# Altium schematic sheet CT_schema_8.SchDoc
size 277 x 170 mm
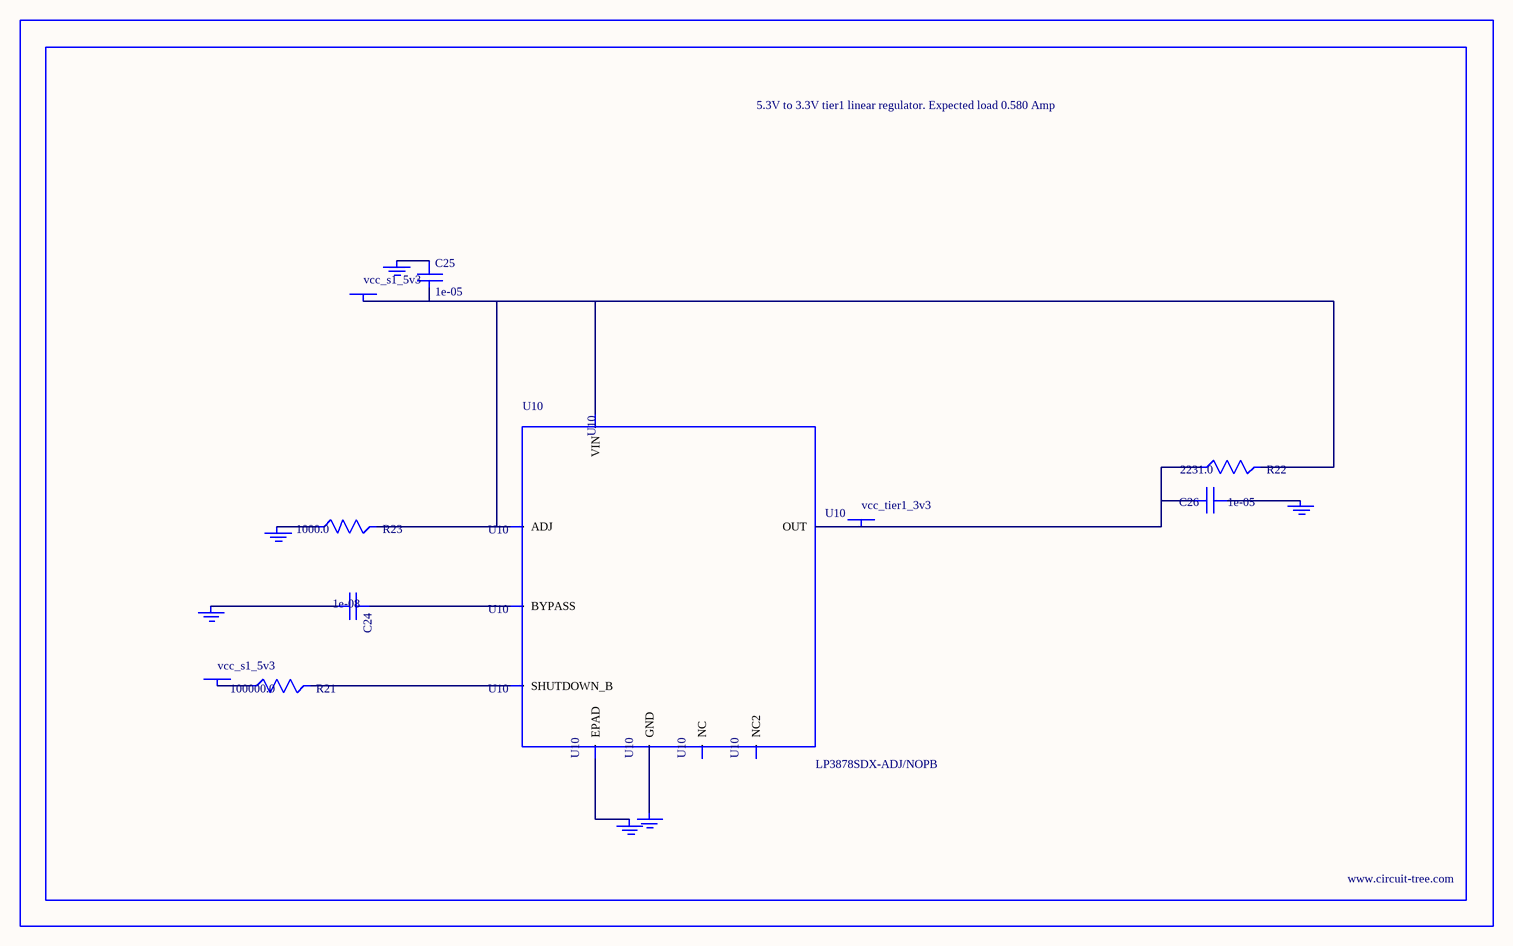
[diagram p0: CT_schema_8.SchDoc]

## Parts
BORDER7  (no value)
C24  1e-08  [C0402]
C25  1e-05  [C1206]
C26  1e-05  [C1210]
GND_INSTANCE_7_0  (no value)
GND_INSTANCE_7_1  (no value)
GND_INSTANCE_7_2  (no value)
GND_INSTANCE_7_3  (no value)
GND_INSTANCE_7_4  (no value)
GND_INSTANCE_7_5  (no value)
POWER_INSTANCE_7_0  vcc_s1_5v3
POWER_INSTANCE_7_1  vcc_s1_5v3
POWER_INSTANCE_7_2  vcc_tier1_3v3
R21  100000.0  [R0603]
R22  2231.0  [R0603]
R23  1000.0  [R0603]
U10  LP3878SDX-ADJ/NOPB  [WSON-8]

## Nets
NetC24_1: C24.1 U10.1(BYPASS)
NetC24_2: C24.2 GND_INSTANCE_7_0.0(GND)
NetC25_1: C25.1 GND_INSTANCE_7_1.0(GND)
NetC25_2: C25.2 POWER_INSTANCE_7_0.0(PWR) R22.2 R23.2 U10.4(VIN) U10.6(ADJ)
NetC26_1: C26.1 GND_INSTANCE_7_2.0(GND)
NetC26_2: C26.2 POWER_INSTANCE_7_2.0(PWR) R22.1 U10.5(OUT)
NetGND_INSTANCE_7_3_0: GND_INSTANCE_7_3.0(GND) R23.1
NetGND_INSTANCE_7_4_0: GND_INSTANCE_7_4.0(GND) U10.PAD(EPAD)
NetGND_INSTANCE_7_5_0: GND_INSTANCE_7_5.0(GND) U10.3(GND)
NetPOWER_INSTANCE_7_1_0: POWER_INSTANCE_7_1.0(PWR) R21.1
NetR21_2: R21.2 U10.8(SHUTDOWN_B)

Not connected (* = marked no-connect by the designer): U10 2(NC) 7(NC2)

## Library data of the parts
BORDER7 = BORDER_PAGE7
C24 = C0402C103K3RAC
C25 = C1206C106K3RACTU
C26 = GRM32DR61E106MA12L
GND_INSTANCE_7_0-GND_INSTANCE_7_5 = GND
POWER_INSTANCE_7_0-POWER_INSTANCE_7_2 = PWR
R21 = RC0603JR-07100KL
R22 = R22
R23 = RC0603JR-071KL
